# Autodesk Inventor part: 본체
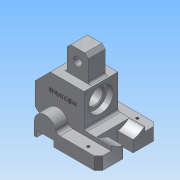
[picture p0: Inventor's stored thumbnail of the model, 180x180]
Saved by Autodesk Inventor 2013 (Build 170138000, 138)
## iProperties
Created: 2016-11
Part Number: 본체
Material: 알루미늄 6061
Document SubType Name: Modeling
Designer: Administrator
Density: 2.71 g/cm^3
Mass: 462.906 g
Surface Area: 317.29 cm^2
Volume: 170.814 cm^3
Author: Administrator
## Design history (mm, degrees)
sketch "스케치1"
  geometry: L1 (-34, -28)-(34, -28); L2 (34, -28)-(34, -20); L3 (20, 20)-(-20, 20); L4 (-38, 2)-(-38, -24); L5 (-20, 20)-(-38, 2); L6 (20, 20)-(20, -20); L7 (20, -20)-(34, -20); L8 (-34, -28)-(-38, -24); 6 further points
  constraints: 16 end point, 5 point on line, 3 parallel, 2 horizontal alignment, 2 midpoint, 2 perpendicular, 1 horizontal, 1 vertical alignment
  dimensions: "d2" = 48 distance of point (-38, 20) point (-38, -28); "d3" = 18 distance of L3.end point (-38, 20); "d4" = 18 distance of L4.start point (-38, 20) (= d3); "d5" = 72 distance of point (-38, -28) L1.end; "d6" = 58 distance between parallel lines of L6 L4; "d7" = 4 distance of L1.start point (-38, -28); "d8" = 4 distance of L4.end point (-38, -28) (= d7); "d10" = 8 distance of L1.end L2.end
extrude "돌출1" new body sketch "스케치1" stored distance "d11" = 40; taper "d12" = 0 deg
sketch "스케치2"
  geometry: L1 (-10, 20)-(15, 20); L2 (15, 20)-(15, 46); L3 (11, 50)-(-6, 50); L4 (-10, 46)-(-10, 20); L5 (-6, 50)-(-10, 46); L6 (11, 50)-(15, 46); L7 (20, 20)-(-20, 20) reference; 3 further points
  constraints: 12 end point, 5 point on line, 2 parallel, 1 horizontal, 1 perpendicular
  dimensions: "d13" = 25 distance of point (15, 50) point (-10, 50); "d15" = 4 distance of L3.end point (-10, 50); "d16" = 4 distance of L4.start point (-10, 50) (= d15); "d17" = 4 distance of L3.start point (15, 50) (= d15); "d18" = 4 distance of L2.end point (15, 50) (= d17); "d19" = 30 distance between parallel lines of L1 L3; "d20" = 5 distance from line of L2 L7.start
extrude "돌출2" join sketch "스케치2" stored distance "d21" = 20; taper "d22" = 0 deg
sketch "스케치3"
  geometry: L1 (0, -8)-(40, -8) reference; 2 further points
  constraints: 1 vertical alignment
  dimensions: "d23" = 30 distance from line of L1 point (20, 22)
hole "구멍1" sketch "스케치3" at (20, 22) diameter "d24" = 20; stored, may be unused: countersink angle "d28" = 90 deg, drill point angle "d30" = 118 deg; dims "d25" = 6, "d26" = 29, "d27" = 7, "d29" = 8
sketch "스케치4"
  geometry: L1 (-10, 46)-(-10, 20) reference; L2 (13, -8)-(13, 12) reference; L3 (13, 2)-(-45.414, 2); 2 further points
  constraints: 2 end point, 1 midpoint, 1 perpendicular
  dimensions: "d31" = 35 distance from line of L3 point (2.5, 37); "d33" = 12.5 distance from line of L1 point (2.5, 37)
hole "구멍2" sketch "스케치4" at (2.5, 37) diameter "d34" = 8; stored, may be unused: countersink angle "d38" = 90 deg, drill point angle "d40" = 118 deg; dims "d35" = 6, "d36" = 8, "d37" = 7, "d39" = 50
chamfer "모따기1" distance "d41" = 1; stored, may be unused: second distance "d42" = 2, angle "d43" = 45 deg
chamfer "모따기2" distance "d44" = 1; stored, may be unused: second distance "d45" = 2, angle "d46" = 45 deg
node "작업 평면1"
sketch "스케치5"
  geometry: L1 (-24, -25)-(-24, -40); L2 (-24, -40)-(-21, -40); L3 (-21, -40)-(-21, -33); L4 (-21, -33)-(-1, -33); L5 (-1, -33)-(-1, -40); L6 (-1, -40)-(34, -40); L7 (34, -40)-(34, -25); L8 (34, -25)-(6.292, -25); L9 (20, 20)-(-20, 20) reference; L10 (-38, 2)-(-38, -24) reference; A1 r 13 centre (-11, -25) between (1.488, -21.389) and (-24, -25); A2 r 5 centre (6.292, -20) between (1.488, -21.389) and (6.292, -25); 2 further points
  constraints: 16 end point, 5 point on circle, 4 parallel, 3 tangent, 2 centre point, 2 collinear, 2 perpendicular, 1 point on line, 1 vertical
  dimensions: "d48" = 26 diameter of A1; "d49" = 15 distance of L6.end L7.end; "d50" = 7 distance of L2.end L3.end; "d51" = 3 distance of L1.end L2.end; "d52" = 20 distance of L3.end L4.end; "d53" = 45 distance from line of L7 A1.centre; "d54" = 15 distance from line of L2 L1.start; "d55" = 5 radius of A2; "d56" = 60 distance between parallel lines of L6 L9; "d57" = 72 distance between parallel lines of L7 L10
extrude "돌출3" join sketch "스케치5" distance "d58" = 70; taper "d59" = 0 deg
sketch "스케치6"
  geometry: L1 (40, 0)-(0, 0) reference; L2 (-15, -20)-(55, -20) reference; L3 (40, -5)-(55, -5) reference; L4 (-15, -5)-(0, -5); L5 (0, -5)-(0, 0); L6 (0, 0)-(1.106, 0); L7 (38.894, 0)-(40, 0); L8 (40, 0)-(40, -5); L9 (40, -5)-(55, -5); L10 (55, -5)-(55, -20); L11 (55, -20)-(26, -20); L12 (26, -20)-(26, -6.373); L13 (-15, -5)-(-15, -20) reference; L14 (-15, -5)-(-15, -20); L15 (-15, -20)-(14, -20); L16 (14, -20)-(14, -6.373); C1 r 10 at (20, 22) reference; A1 r 29 centre (20, 22) between (26, -6.373) and (38.894, 0); A2 r 29 centre (20, 22) between (1.106, 0) and (14, -6.373); 1 further point
  constraints: 24 end point, 6 perpendicular, 4 point on circle, 4 point on line, 2 centre point, 2 collinear, 1 coincident
  dimensions: "d61" = 29 distance of L2.end L11.end; "d62" = 29 distance of L2.start L15.end; "d63" = 29 radius of A2; "d64" = 29 radius of A1
extrude "돌출4" join sketch "스케치6" distance "d65" = 18; taper "d66" = 0 deg
sketch "스케치7"
  geometry: L1 (20, -20)-(20, 20) reference; L2 (20, 20)-(-20, 20) reference; 2 further points
  constraints: 1 other
  dimensions: "d67" = 25 distance from line of L1 point (-5, 2); "d68" = 18 distance from line of point (-5, 2) L2
feature "엠보싱1" sketch "스케치7" dims "d69" = 0.5, "d70" = 0
fillet "모깎기1" dims "d71" = 3
chamfer "모따기3" distance "d72" = 5; stored, may be unused: second distance "d73" = 2, angle "d74" = 45 deg
sketch "스케치8"
  geometry: L1 (45.708, 15)-(45.708, 5) reference; L2 (27.708, 29)-(27.708, 41) reference; L3 (27.708, 35)-(-47.396, 35); L4 (45.708, 41)-(45.708, 65) reference; 3 further points
  constraints: 2 end point, 1 midpoint, 1 perpendicular
  dimensions: "d75" = 18 distance from line of L1 point (27.708, 6); "d76" = 29 distance from line of L3 point (27.708, 6); "d85" = 18 distance from line of L4 point (27.708, 64); "d86" = 29 distance from line of L3 point (27.708, 64)
hole "구멍3" sketch "스케치8" at (27.708, 6), (27.708, 64) diameter "d77" = 3.242; stored, may be unused: countersink angle "d81" = 90 deg, drill point angle "d83" = 118 deg; dims "d78" = 6, "d79" = 8, "d80" = 7, "d82" = 8
fillet "모깎기2" dims "d84" = 3
node "솔리드1"
other parameters: "d47" = 15, "d60" = 58
